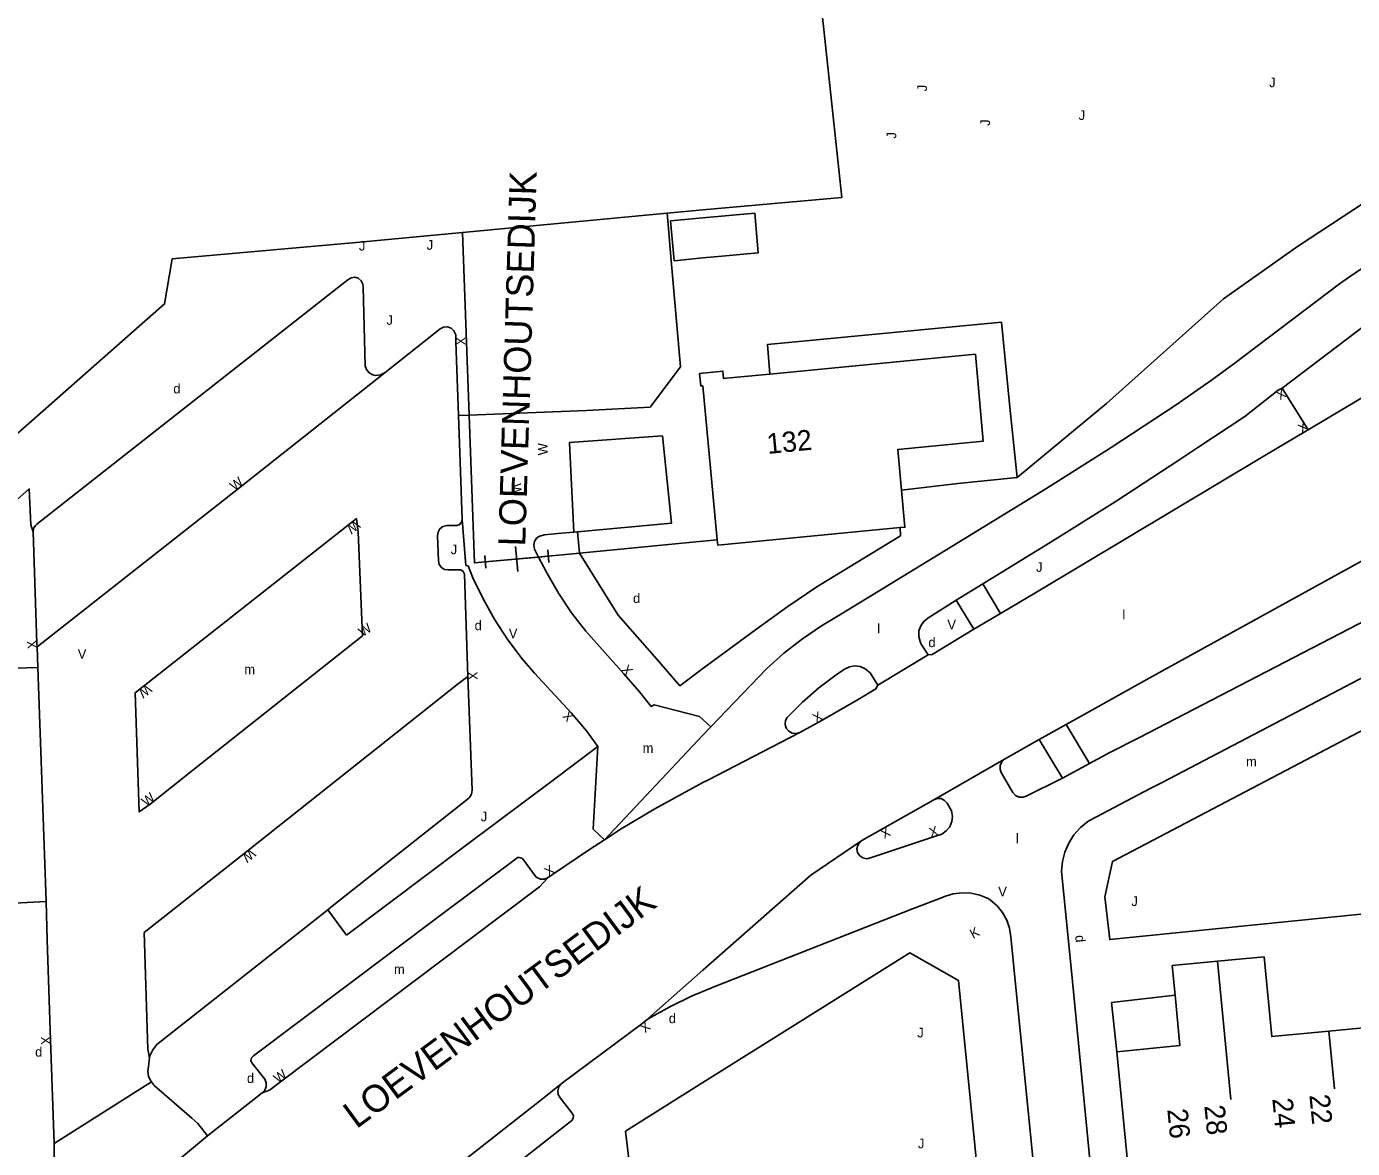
# Model space of a CAD drawing. Extents: x 134999 to 136502, y 457398 to 459002.
# Drawn here: x 135965 to 136033.6, y 457742 to 457800.2 of the extents above; entities that cross this region are included whole.
import ezdxf

# ---------------------------------------------------------------- set-up
doc = ezdxf.new("R2010")
doc.units = 0
for name, color, linetype in [('RI_DGTB_15', 7, 'Continuous'), ('RI_DGTB_29', 7, 'Continuous'), ('RI_DGTB_30', 7, 'Continuous'), ('RI_DGTB_31', 7, 'Continuous'), ('RI_DGTB_35', 7, 'Continuous'), ('RI_DGTB_36', 7, 'Continuous'), ('RI_DGTB_37', 7, 'Continuous'), ('RI_DGTB_4', 7, 'Continuous'), ('RI_DGTB_43', 7, 'Continuous'), ('RI_DGTB_48', 7, 'Continuous'), ('RI_DGTB_53', 7, 'Continuous'), ('RI_DGTB_54', 7, 'Continuous'), ('RI_DGTB_6', 7, 'Continuous')]:
    doc.layers.add(name, color=color, linetype=linetype)

msp = doc.modelspace()

# ---------------------------------------------------------------- linework, layer by layer
at = {"layer": 'RI_DGTB_15'}
for p, q in [((136026.649, 457751.71), (136027.347, 457744.556)), ((136032.42, 457748.093), (136032.713, 457745.106))]:
    msp.add_line(p, q, dxfattribs=at)
at = {"layer": 'RI_DGTB_4'}
for p, q in [((136000.744, 457773.561), (136000, 457781.541)), ((136003.47, 457782.142), (136001.772, 457781.978)), ((136000.744, 457773.561), (136000.77, 457773.286)), ((136022.437, 457736.685), (136021.432, 457747.026))]:
    msp.add_line(p, q, dxfattribs=at)
for points in [[(136003.47, 457782.142), (136014.116, 457783.171), (136014.517, 457778.671), (136010.099, 457778.238), (136010.287, 457776.126)], [(136000, 457781.541), (135999.889, 457781.53), (135999.829, 457782.182), (136000, 457782.199)], [(136000, 457782.199), (136001.031, 457782.298), (136001.069, 457781.91), (136001.772, 457781.978)], [(136010.209, 457774.187), (136010.458, 457774.211), (136010.287, 457776.126)], [(136000.77, 457773.286), (136010.209, 457774.187)], [(136032.42, 457748.095), (136035.457, 457748.389), (136035.055, 457752.518), (136037.37, 457752.745)], [(136026.649, 457751.71), (136024.304, 457751.489), (136024.451, 457749.962)], [(136032.42, 457748.095), (136029.462, 457747.808), (136029.062, 457751.938), (136026.649, 457751.71)], [(136021.432, 457747.026), (136024.702, 457747.346), (136024.451, 457749.962)]]:
    msp.add_lwpolyline(points, dxfattribs=at)
at = {"layer": 'RI_DGTB_48'}
for p, q in [((136000, 457790.655), (135998.146, 457790.48)), ((135972.515, 457788.117), (135982.033, 457788.961)), ((136000, 457773.488), (136000.744, 457773.561)), ((135988.756, 457772.088), (135988.698, 457772.741)), ((135988.727, 457772.415), (135991.987, 457772.705)), ((135990.415, 457771.908), (135990.298, 457773.213)), ((135992.016, 457772.379), (135991.958, 457773.031))]:
    msp.add_line(p, q, dxfattribs=at)
for points in [[(136095.97, 457853.01), (136094.74, 457853.382), (136092.4, 457845.7), (136083.4, 457841.07), (136044.121, 457821.151), (136033.472, 457815.274), (136005.423, 457809.755), (136005.752, 457805.109), (136006.042, 457802.024), (136006.259, 457800)], [(136006.259, 457800), (136007.193, 457791.301), (136000, 457790.655)], [(135987.547, 457789.481), (135998.146, 457790.48)], [(135982.033, 457788.961), (135987.547, 457789.481)], [(135987.547, 457789.481), (135987.886, 457780.02)], [(135960.12, 457775.174), (135962.016, 457776.888), (135972.114, 457785.782), (135972.515, 457788.117)], [(136016.279, 457776.789), (136015.891, 457780.429), (136015.466, 457784.831), (136003.336, 457783.672), (136003.47, 457782.142)], [(135987.886, 457780.02), (135988.16, 457772.36), (135988.727, 457772.415)], [(136016.279, 457776.789), (136013.205, 457776.471), (136010.287, 457776.126)], [(135993.61, 457772.864), (136000, 457773.488)], [(135988.727, 457772.415), (135991.488, 457772.661)], [(135991.488, 457772.661), (135991.987, 457772.705)], [(135991.987, 457772.705), (135993.61, 457772.864)]]:
    msp.add_lwpolyline(points, dxfattribs=at)
at = {"layer": 'RI_DGTB_53'}
for p, q in [((135982.399, 457786.661), (135982.512, 457782.577)), ((135983.54, 457782.219), (135986.392, 457784.487)), ((136029.996, 457781.421), (136031.342, 457779.255)), ((135987.274, 457774.298), (135986.73, 457774.294)), ((135993.493, 457773.97), (135993.32, 457773.955)), ((135986.256, 457773.762), (135986.306, 457772.473)), ((135986.805, 457771.999), (135987.296, 457772.001)), ((136014.492, 457771.269), (136013.114, 457770.43)), ((136015.407, 457769.738), (136014.034, 457768.92)), ((136011.307, 457768.152), (136011.664, 457767.601)), ((136009.061, 457766.016), (136011.664, 457767.601)), ((136017.422, 457763.204), (136018.82, 457763.992)), ((136021.213, 457756.888), (136035.021, 457764.132)), ((135994.893, 457758.01), (136000, 457763.423)), ((136011.956, 457760.088), (136015.624, 457762.188)), ((136018.626, 457761.201), (136020.028, 457761.958)), ((136015.443, 457761.498), (136016.056, 457760.451)), ((136023.165, 457760.668), (136023.793, 457760.97)), ((136020.053, 457759.032), (136023.165, 457760.668)), ((136012.65, 457759.9), (136012.874, 457759.512)), ((136008.231, 457757.972), (136005.593, 457756.174)), ((135991.359, 457756.076), (135990.647, 457757.046)), ((136021.213, 457756.888), (136020.823, 457755.06)), ((136005.593, 457756.174), (136000, 457751.251)), ((135981.544, 457753.07), (135980.563, 457754.384)), ((136000, 457751.251), (135997.022, 457748.629)), ((135971.327, 457746.709), (135971.283, 457746.258)), ((135976.634, 457746.444), (135977.305, 457745.599)), ((135971.432, 457745.472), (135966.401, 457742.261)), ((135992.599, 457744.637), (135993.212, 457743.855)), ((135995.992, 457742.915), (135996.821, 457735.997)), ((135966.401, 457742.261), (135966.403, 457741.569))]:
    msp.add_line(p, q, dxfattribs=at)
for points in [[(136023.793, 457760.97), (136035.091, 457766.906), (136052.351, 457776.008), (136068.76, 457784.651), (136078.139, 457789.59), (136097.898, 457800)], [(136049.083, 457793.609), (136045.634, 457791.566), (136035.653, 457785.595), (136034.796, 457785.055), (136029.996, 457781.421)], [(136031.342, 457779.255), (136038.36, 457783.439), (136047.069, 457788.662), (136050.725, 457790.861)], [(136036.821, 457789.33), (136035.134, 457788.293), (136033.492, 457787.188), (136032.97, 457786.817)], [(135965.503, 457774.37), (135970.988, 457778.68), (135981.295, 457786.787), (135981.609, 457787.034)], [(135981.609, 457787.034), (135981.773, 457787.135), (135981.964, 457787.161), (135982.149, 457787.108), (135982.298, 457786.985), (135982.384, 457786.813), (135982.399, 457786.661)], [(136032.97, 457786.817), (136027.505, 457782.678), (136026.347, 457781.822)], [(135986.392, 457784.487), (135986.565, 457784.576), (135986.763, 457784.59), (135986.95, 457784.525), (135987.097, 457784.392), (135987.192, 457784.184)], [(135987.192, 457784.184), (135987.194, 457783.825), (135987.345, 457779.998)], [(135965.514, 457768.007), (135975.938, 457776.223), (135983.54, 457782.219)], [(135982.512, 457782.577), (135982.576, 457782.376), (135982.711, 457782.209), (135982.897, 457782.101), (135983.026, 457782.072)], [(135983.026, 457782.072), (135983.291, 457782.106), (135983.54, 457782.219)], [(136026.347, 457781.822), (136024.507, 457780.556), (136021.144, 457778.342), (136017.765, 457776.192), (136013.48, 457773.573), (136007.17, 457769.711)], [(136029.996, 457781.421), (136029.795, 457781.305), (136028.059, 457779.941), (136025.626, 457778.334)], [(135993.96, 457780.266), (135987.886, 457780.02)], [(135987.886, 457780.02), (135987.345, 457779.998)], [(135987.345, 457779.998), (135987.391, 457778.558), (135987.529, 457774.617)], [(135993.083, 457778.601), (135997.897, 457778.939), (135998.369, 457774.414), (135993.493, 457773.97)], [(136029.11, 457777.921), (136031.231, 457779.189), (136031.342, 457779.255)], [(135993.32, 457773.955), (135993.104, 457778.202), (135993.083, 457778.601)], [(136025.626, 457778.334), (136024.699, 457777.722)], [(136014.492, 457771.269), (136017.98, 457773.418), (136021.348, 457775.522), (136024.699, 457777.722)], [(136015.407, 457769.738), (136017.273, 457770.842), (136029.11, 457777.921)], [(136018.82, 457763.992), (136023.265, 457766.478), (136032.877, 457771.782), (136034.83, 457772.846), (136042.086, 457776.755), (136043.771, 457777.645)], [(135965.304, 457773.964), (135965.187, 457774.325), (135965.105, 457776.193), (135963.309, 457774.606)], [(135973.579, 457761.616), (135971.367, 457759.863), (135970.803, 457759.452), (135970.597, 457765.629), (135971.006, 457765.949), (135981.79, 457774.454), (135982.052, 457774.656), (135982.143, 457773.947), (135982.361, 457768.574), (135973.579, 457761.616)], [(136020.028, 457761.958), (136021.069, 457762.527), (136022.582, 457763.287), (136033.931, 457769.19), (136045.108, 457775.127)], [(135965.304, 457773.964), (135965.327, 457774.148), (135965.424, 457774.306), (135965.503, 457774.37)], [(135965.514, 457768.007), (135965.494, 457768.18), (135965.304, 457773.964)], [(135986.73, 457774.294), (135986.534, 457774.245), (135986.376, 457774.125), (135986.278, 457773.953), (135986.256, 457773.762)], [(135987.529, 457774.617), (135987.499, 457774.465), (135987.398, 457774.348), (135987.274, 457774.298)], [(135987.529, 457774.617), (135987.719, 457772.227), (135987.834, 457772.213), (135988.085, 457771.587)], [(135991.504, 457773.729), (135991.78, 457773.815), (135992.487, 457773.888), (135993.32, 457773.955)], [(135993.493, 457773.97), (135993.61, 457772.864)], [(136006.119, 457771.251), (136010.228, 457773.769), (136010.209, 457774.187)], [(135991.277, 457773.077), (135991.232, 457773.27), (135991.266, 457773.466), (135991.374, 457773.633), (135991.504, 457773.729)], [(135991.488, 457772.661), (135991.277, 457773.077)], [(135991.756, 457772.132), (135991.488, 457772.661)], [(135993.61, 457772.864), (135995.616, 457769.642), (135997.732, 457767.231), (135998.804, 457765.993), (136000, 457766.878)], [(135986.306, 457772.473), (135986.344, 457772.283), (135986.455, 457772.125), (135986.62, 457772.024), (135986.805, 457771.999)], [(135987.296, 457772.001), (135987.46, 457771.993), (135987.58, 457771.912), (135987.643, 457771.777)], [(135993.931, 457768.823), (135993.195, 457769.778), (135992.518, 457770.787), (135991.91, 457771.838), (135991.756, 457772.132)], [(135987.643, 457771.777), (135987.822, 457766.472)], [(135988.085, 457771.587), (135988.613, 457770.491), (135989.219, 457769.414), (135989.894, 457768.379), (135990.634, 457767.389), (135991.266, 457766.641)], [(136002.724, 457768.895), (136004.337, 457770.072), (136005.898, 457771.112), (136006.119, 457771.251)], [(136014.492, 457771.269), (136015.407, 457769.738)], [(136013.114, 457770.43), (136011.655, 457769.499)], [(136014.034, 457768.92), (136013.114, 457770.43)], [(136007.17, 457769.711), (136006.146, 457769.106), (136005.147, 457768.423), (136004.195, 457767.676), (136003.294, 457766.868), (136002.475, 457766.03)], [(136011.655, 457769.499), (136011.44, 457769.326), (136011.279, 457769.096), (136011.189, 457768.83), (136011.177, 457768.55), (136011.245, 457768.277), (136011.307, 457768.152)], [(135997.477, 457765.005), (135997.323, 457764.909), (135996.711, 457765.678), (135995.897, 457766.615), (135993.931, 457768.823)], [(136000, 457766.878), (136002.724, 457768.895)], [(136011.664, 457767.601), (136011.878, 457767.604), (136014.034, 457768.92)], [(135965.542, 457766.945), (135965.514, 457768.007)], [(135965.979, 457754.807), (135963.665, 457754.697), (135963.245, 457766.868), (135965.542, 457766.945)], [(135965.979, 457754.807), (135965.542, 457766.945)], [(135987.822, 457766.472), (135987.333, 457766.112), (135976.383, 457757.427), (135971.048, 457753.203), (135971.226, 457747.698)], [(135987.822, 457766.472), (135988.045, 457760.586)], [(135991.266, 457766.641), (135993.182, 457764.597), (135993.961, 457763.662), (135994.558, 457762.842)], [(136004.361, 457764.343), (136005.153, 457765.142), (136005.999, 457765.882), (136006.896, 457766.56), (136007.336, 457766.857)], [(136007.336, 457766.857), (136007.591, 457766.977), (136007.869, 457767.021), (136008.149, 457766.986), (136008.408, 457766.874), (136008.667, 457766.659)], [(136008.667, 457766.659), (136009.061, 457766.016)], [(136002.475, 457766.03), (136000.414, 457763.862)], [(136009.061, 457766.016), (136008.96, 457765.832), (136008.037, 457765.28), (136006.083, 457764.163), (136005.011, 457763.564)], [(136000, 457764.238), (135999.82, 457764.401), (135997.477, 457765.005)], [(136005.011, 457763.564), (136004.82, 457763.509), (136004.618, 457763.532), (136004.44, 457763.631), (136004.313, 457763.789), (136004.257, 457763.985), (136004.28, 457764.187), (136004.361, 457764.343)], [(136000.414, 457763.862), (136000, 457764.238)], [(136000.414, 457763.862), (136000, 457763.423)], [(136018.82, 457763.992), (136020.028, 457761.958)], [(136005.011, 457763.564), (136000.244, 457761.104), (136000, 457760.97)], [(136017.422, 457763.204), (136015.624, 457762.188)], [(136018.626, 457761.201), (136017.422, 457763.204)], [(135994.558, 457762.842), (135992.244, 457761.092), (135987.804, 457757.786), (135981.544, 457753.07)], [(135994.893, 457758.01), (135994.313, 457758.559), (135994.558, 457762.842)], [(136015.624, 457762.188), (136015.476, 457762.044), (136015.395, 457761.856), (136015.39, 457761.651), (136015.443, 457761.498)], [(136000, 457760.97), (135997.512, 457759.608)], [(136016.739, 457760.27), (136018.626, 457761.201)], [(135988.045, 457760.586), (135988.011, 457760.376), (135987.902, 457760.193), (135987.869, 457760.158)], [(136016.056, 457760.451), (136016.196, 457760.307), (136016.384, 457760.224), (136016.589, 457760.22), (136016.739, 457760.27)], [(135987.869, 457760.158), (135980.798, 457754.569), (135980.563, 457754.384)], [(135997.512, 457759.608), (135995.769, 457758.568), (135994.893, 457758.01)], [(136008.231, 457757.972), (136009.305, 457758.578), (136011.956, 457760.088)], [(136011.956, 457760.088), (136012.143, 457760.154), (136012.341, 457760.142), (136012.519, 457760.053), (136012.648, 457759.902), (136012.65, 457759.9)], [(136012.874, 457759.512), (136012.921, 457759.23), (136012.889, 457758.948), (136012.779, 457758.687), (136012.602, 457758.466), (136012.369, 457758.303), (136012.272, 457758.26)], [(136018.571, 457756.377), (136018.617, 457756.875), (136018.743, 457757.366), (136018.945, 457757.831), (136019.216, 457758.258), (136019.552, 457758.637), (136019.943, 457758.959), (136020.053, 457759.032)], [(136012.272, 457758.26), (136012.041, 457758.194), (136008.678, 457757.072)], [(135994.893, 457758.01), (135994.063, 457757.478), (135992.214, 457756.215), (135991.986, 457756.047)], [(136008.678, 457757.072), (136008.482, 457757.03), (136008.287, 457757.068), (136008.121, 457757.18), (136008.011, 457757.347), (136007.975, 457757.543), (136008.019, 457757.738), (136008.134, 457757.901), (136008.231, 457757.972)], [(135990.421, 457757.112), (135986.324, 457754.034), (135976.716, 457746.809)], [(135990.647, 457757.046), (135990.421, 457757.112)], [(136020.373, 457738.05), (136019.132, 457750.656), (136018.571, 457756.377)], [(135991.986, 457756.047), (135991.53, 457755.562), (135987.914, 457752.84), (135978.194, 457745.519), (135977.541, 457745.038), (135977.172, 457744.9)], [(135991.986, 457756.047), (135991.796, 457755.972), (135991.593, 457755.975), (135991.359, 457756.076)], [(135966.401, 457742.261), (135966.213, 457747.64), (135966.039, 457752.812), (135965.979, 457754.807)], [(136012.446, 457755.04), (136010.845, 457754.422), (136000.619, 457750.403)], [(136014.767, 457754.962), (136014.338, 457755.14), (136013.886, 457755.241), (136013.423, 457755.264), (136012.962, 457755.206), (136012.519, 457755.071), (136012.446, 457755.04)], [(136015.942, 457752.977), (136015.875, 457753.42), (136015.731, 457753.846), (136015.514, 457754.239), (136015.23, 457754.587), (136014.89, 457754.879), (136014.767, 457754.962)], [(135980.563, 457754.384), (135971.718, 457747.397)], [(136017.44, 457737.885), (136016.11, 457751.41), (136015.942, 457752.977)], [(136014.513, 457737.82), (136013.232, 457750.716), (136010.716, 457752.142), (136003.5, 457747.621), (136000, 457745.427)], [(136000, 457750.147), (135999.435, 457749.914), (135998.284, 457749.353), (135997.17, 457748.721), (135997.022, 457748.629)], [(136000.618, 457750.403), (136000, 457750.147)], [(135997.022, 457748.629), (135996.832, 457748.478), (135992.661, 457745.358)], [(135971.226, 457747.698), (135971.252, 457747.154), (135971.327, 457746.709)], [(135971.718, 457747.397), (135971.503, 457747.122), (135971.356, 457746.806), (135971.327, 457746.709)], [(135976.716, 457746.809), (135976.616, 457746.703), (135976.588, 457746.563), (135976.634, 457746.444)], [(135971.283, 457746.258), (135971.239, 457746.008), (135971.275, 457745.757), (135971.387, 457745.53), (135971.432, 457745.472)], [(135974.331, 457742.661), (135973.83, 457743.303), (135973.528, 457743.586), (135971.569, 457745.278), (135971.432, 457745.472)], [(135992.661, 457745.358), (135992.126, 457744.92), (135991.693, 457744.579), (135985.202, 457739.478), (135975.552, 457731.892)], [(135977.305, 457745.599), (135977.382, 457745.41), (135977.379, 457745.21), (135977.299, 457745.027), (135977.172, 457744.9)], [(135992.661, 457745.358), (135992.536, 457745.198), (135992.482, 457745.003), (135992.507, 457744.803), (135992.599, 457744.637)], [(136000, 457745.427), (135995.992, 457742.915)], [(135977.172, 457744.9), (135976.268, 457744.189), (135974.331, 457742.661)], [(135993.212, 457743.855), (135993.287, 457743.723), (135993.282, 457743.578), (135993.201, 457743.456)], [(135993.201, 457743.456), (135992.811, 457743.155), (135986.322, 457738.054), (135976.671, 457730.468)], [(135974.331, 457742.661), (135965.485, 457735.283)]]:
    msp.add_lwpolyline(points, dxfattribs=at)
at = {"layer": 'RI_DGTB_54'}
for p, q in [((135998.146, 457790.48), (135998.18, 457790.086)), ((135998.18, 457790.086), (135998.36, 457788.029))]:
    msp.add_line(p, q, dxfattribs=at)
for points in [[(136049.819, 457800), (136043.73, 457796.624), (136041.882, 457795.467), (136037.542, 457792.862), (136034.323, 457791.076), (136030.788, 457788.763), (136026.961, 457786.044), (136020.907, 457780.612), (136016.279, 457776.789)], [(135998.36, 457788.029), (135998.841, 457782.526), (135997.259, 457780.431), (135993.96, 457780.266)], [(136036.275, 457761.907), (136039.898, 457754.737), (136021.074, 457752.839), (136020.823, 457755.06)], [(136024.451, 457749.962), (136021.165, 457749.571), (136021.432, 457747.026)]]:
    msp.add_lwpolyline(points, dxfattribs=at)
at = {"layer": 'RI_DGTB_6'}
msp.add_line((136000, 457788.162), (136000.985, 457788.255), dxfattribs=at)
for points in [[(136000, 457790.239), (136002.681, 457790.491), (136002.861, 457788.431), (136000.985, 457788.255)], [(136000, 457788.162), (135998.504, 457788.02), (135998.324, 457790.081), (136000, 457790.239)]]:
    msp.add_lwpolyline(points, dxfattribs=at)

# ---------------------------------------------------------------- texts
at = {"layer": 'RI_DGTB_29'}
for p in [(135972.568, 457781.145), (135988.174, 457768.871), (136011.677, 457767.993), (135998.228, 457748.507), (135965.408, 457746.768), (135976.381, 457745.404)]:
    msp.add_text('d', height=0.5, dxfattribs=at).set_placement(p)
for rotation, p in [(359.99963, (135996.38, 457770.28)), (275.94788, (136019.275, 457753.04))]:
    msp.add_text('d', height=0.5, rotation=rotation, dxfattribs=at).set_placement(p)
at = {"layer": 'RI_DGTB_30'}
for s, height, rotation, p in [('X', 0.5, 270.30256, (135987.193, 457784.075)), ('X', 0.5, 210.17361, (136030.011, 457781.431)), ('X', 0.5, 30.87018, (136031.013, 457779.055)), ('W', 0.499, 91.53351, (135991.963, 457777.946)), ('W', 0.5, 38.24696, (135975.742, 457776.068)), ('W', 0.5, 276.33966, (135990.071, 457776.441)), ('W', 0.5, 218.26254, (135981.986, 457774.609)), ('W', 0.5, 33.789, (135982.369, 457768.509)), ('X', 0.5, 96.49164, (135965.522, 457767.932)), ('X', 0.5, 310.96179, (135995.733, 457766.804)), ('X', 0.5, 271.93471, (135987.814, 457766.722)), ('W', 0.5, 218.06853, (135971.203, 457766.103)), ('X', 0.5, 133.15836, (135993.353, 457764.415)), ('X', 0.5, 29.76553, (136005.866, 457764.039)), ('W', 0.5, 38.41051, (135971.171, 457759.708)), ('X', 0.5, 209.43443, (136009.523, 457758.701)), ('X', 0.5, 16.1087, (136011.801, 457758.125)), ('W', 0.5, 218.42017, (135976.579, 457757.582)), ('X', 0.5, 34.32721, (135992.008, 457756.074)), ('K', 0.499, 28.32623, (136013.99, 457752.869)), ('X', 0.5, 218.56051, (135997.027, 457748.634)), ('X', 0.5, 92.09569, (135966.222, 457747.39)), ('W', 0.5, 36.98585, (135977.994, 457745.369))]:
    msp.add_text(s, height=height, rotation=rotation, dxfattribs=at).set_placement(p)
for p in [(136012.66, 457768.909), (135989.944, 457768.455), (135967.619, 457767.388), (136015.294, 457755.071)]:
    msp.add_text('V', height=0.5, dxfattribs=at).set_placement(p)
at = {"layer": 'RI_DGTB_31'}
for p in [(136029.326, 457797.015), (136019.46, 457795.313), (135982.181, 457788.547), (135985.691, 457788.587), (135983.607, 457784.698), (135986.936, 457772.808), (136017.256, 457771.897), (135988.494, 457758.965), (136022.189, 457754.575), (136011.098, 457747.765), (136011.133, 457742.018)]:
    msp.add_text('J', height=0.5, dxfattribs=at).set_placement(p)
for p in [(136011.605, 457796.8), (136014.868, 457795.009), (136010.014, 457794.351)]:
    msp.add_text('J', height=0.5, rotation=90, dxfattribs=at).set_placement(p)
at = {"layer": 'RI_DGTB_35'}
for s, rotation, p in [('132', 5.485, (136003.351, 457778.004)), ('26', 275.5881, (136024.048, 457744.034))]:
    msp.add_text(s, height=1.054, rotation=rotation, dxfattribs=at).set_placement(p)
at = {"layer": 'RI_DGTB_36'}
for s, p in [('24', (136029.487, 457744.587)), ('22', (136031.408, 457744.775)), ('28', (136025.969, 457744.223))]:
    msp.add_text(s, height=1.054, rotation=275.5881, dxfattribs=at).set_placement(p)
at = {"layer": 'RI_DGTB_37'}
for rotation, p in [(88.23716, (135990.794, 457773.2)), (36.51311, (135982.05, 457743))]:
    msp.add_text('LOEVENHOUTSEDIJK', height=1.4, rotation=rotation, dxfattribs=at).set_placement(p)
at = {"layer": 'RI_DGTB_43'}
for s, p in [('l', (136021.723, 457769.426)), ('l', (136009.023, 457768.707)), ('m', (135976.243, 457766.589)), ('m', (135996.874, 457762.515)), ('m', (136028.127, 457761.816)), ('l', (136016.212, 457757.831)), ('m', (135983.996, 457751.05))]:
    msp.add_text(s, height=0.5, dxfattribs=at).set_placement(p)

doc.saveas('drawing.dxf')
